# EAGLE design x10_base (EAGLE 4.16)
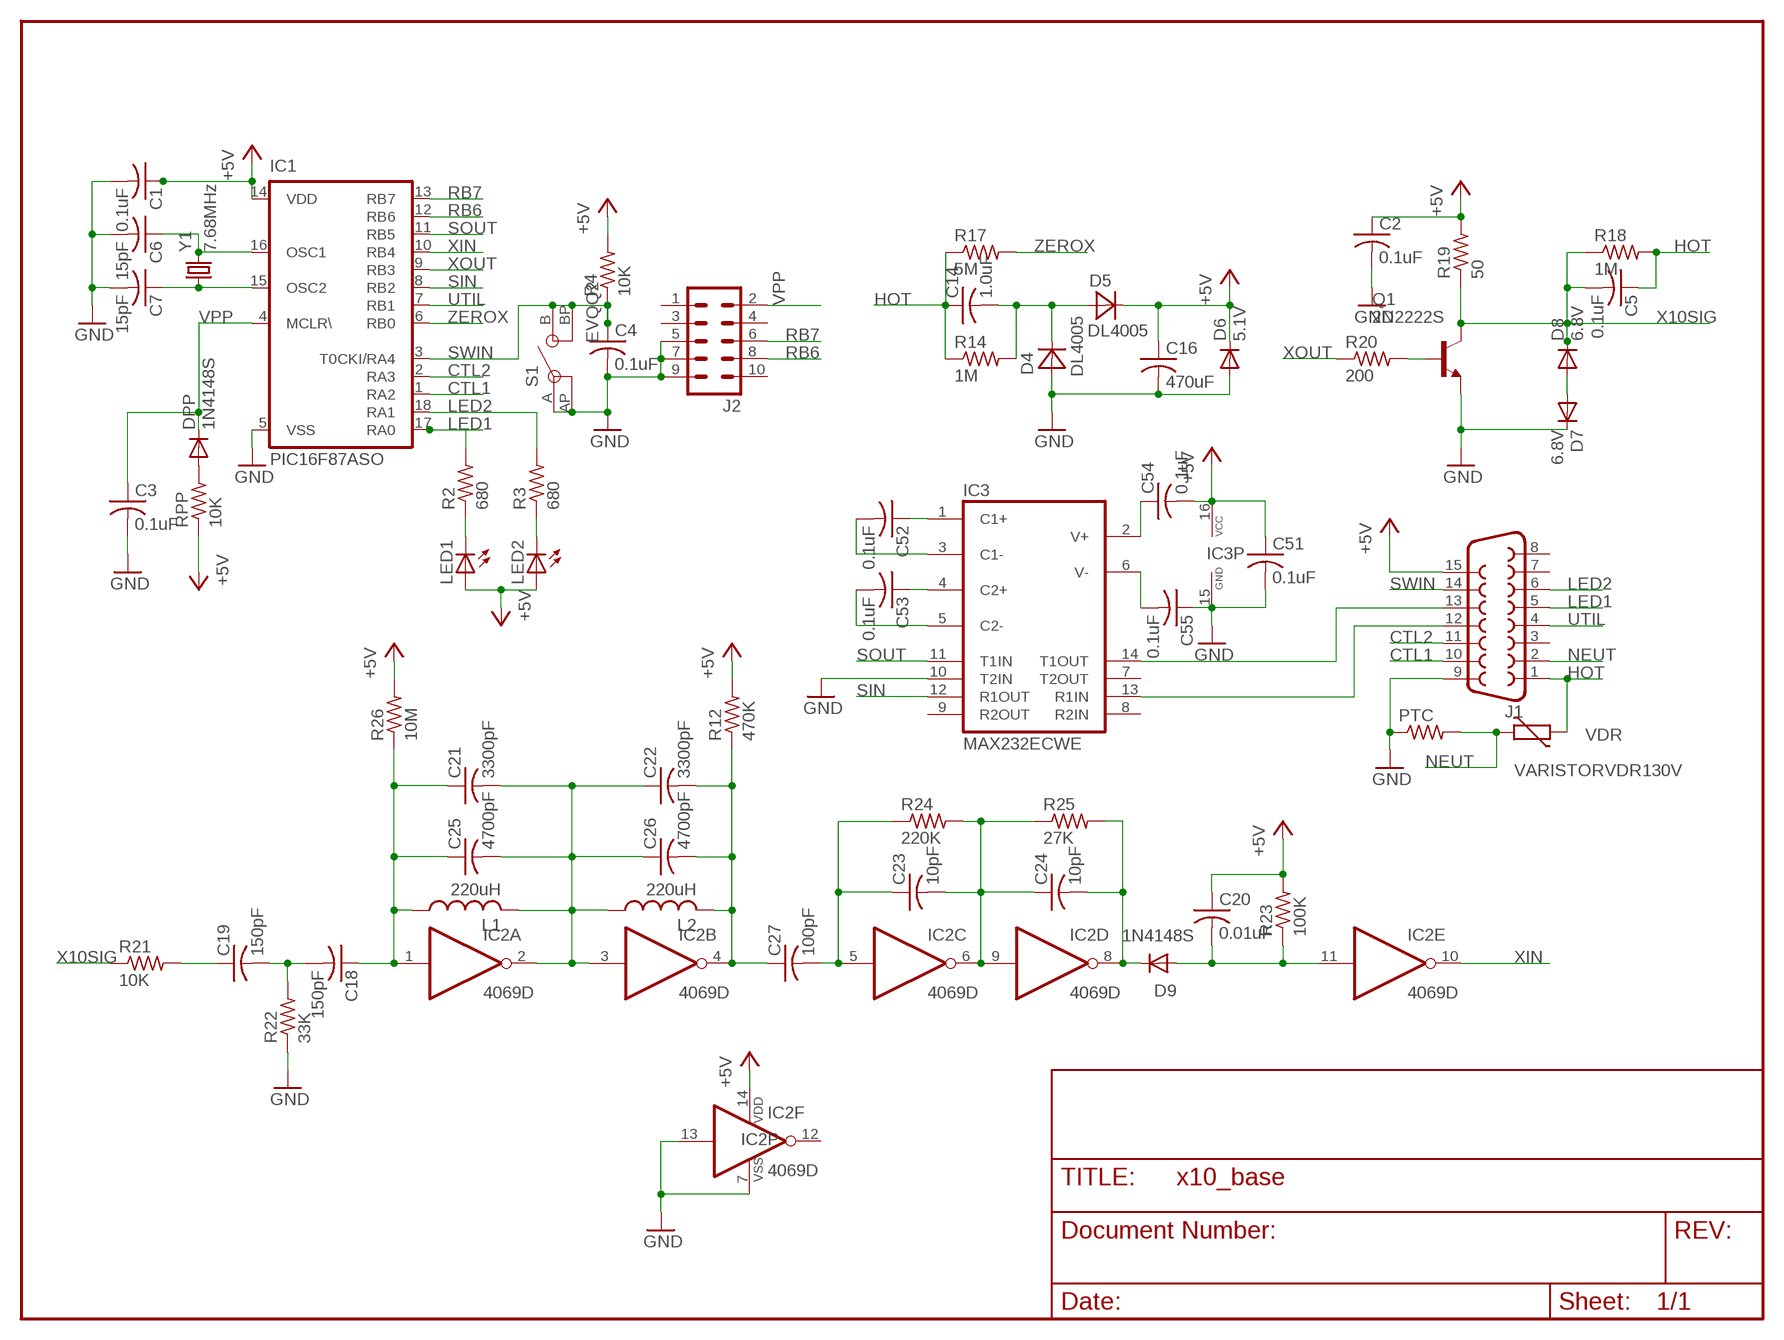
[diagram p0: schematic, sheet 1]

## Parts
C1  0.1uF  C-USC0805  [C0805]
C2  0.1uF  C-USC0805  [C0805]
C3  0.1uF  C-USC0805  [C0805]
C4  0.1uF  C-USC0805  [C0805]
C5  0.1uF  C-US102-043X133  [C102-043X133]
C6  15pF  C-USC0805  [C0805]
C7  15pF  C-USC0805  [C0805]
C14  1.0uF  C-US225-062X268  [C225-062X268]
C16  470uF  C-US275-093X316  [C275-093X316]
C18  150pF  C-USC0805  [C0805]
C19  150pF  C-USC0805  [C0805]
C20  0.01uF  C-USC0805  [C0805]
C21  3300pF  C-USC0805  [C0805]
C22  3300pF  C-USC0805  [C0805]
C23  10pF  C-USC0805  [C0805]
C24  10pF  C-USC0805  [C0805]
C25  4700pF  C-USC0805  [C0805]
C26  4700pF  C-USC0805  [C0805]
C27  100pF  C-USC0805  [C0805]
C51  0.1uF  C-USC0805  [C0805]
C52  0.1uF  C-USC0805  [C0805]
C53  0.1uF  C-USC0805  [C0805]
C54  0.1uF  C-USC0805  [C0805]
C55  0.1uF  C-USC0805  [C0805]
D4  DL4005  [MELF-MLL41]
D5  DL4005  [MELF-MLL41]
D6  5.1V  DIODE-SOD123  [SOD123]
D7  6.8V  DIODE-SOD123  [SOD123]
D8  6.8V  DIODE-SOD123  [SOD123]
D9  1N4148S  [SOD123]
DPP  1N4148S  [SOD123]
IC1  PIC16F87ASO  PIC16F84ASO  [SO-18W]
IC2  4069D  [SO14]
IC3  MAX232ECWE  [SO16L]
J1  F15V  [F15V]
J2  MA05-2  [MA05-2]
L1  220uH  L-US1210  [L1210]
L2  220uH  L-US1210  [L1210]
LED1  LED5MM  [LED5MM]
LED2  LED5MM  [LED5MM]
PTC  R-US_M1206  [M1206]
Q1  2N2222S  [SOT23]
R2  680  R-US_M0805  [M0805]
R3  680  R-US_M0805  [M0805]
R4  10K  R-US_M0805  [M0805]
R12  470K  R-US_M0805  [M0805]
R14  1M  R-US_M0805  [M0805]
R17  5M  R-US_M0805  [M0805]
R18  1M  R-US_M0805  [M0805]
R19  50  R-US_M0805  [M0805]
R20  200  R-US_M0805  [M0805]
R21  10K  R-US_M0805  [M0805]
R22  33K  R-US_M0805  [M0805]
R23  100K  R-US_M0805  [M0805]
R24  220K  R-US_M0805  [M0805]
R25  27K  R-US_M0805  [M0805]
R26  10M  R-US_M0805  [M0805]
RPP  10K  R-US_M0805  [M0805]
S1  EVQQ2  [EVQQ2]
VDR  VARISTORVDR130V  [VDR130V]
Y1  7.68MHz  CRYSTALMM39SL  [MM39SL]

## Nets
+5V: C1.1 C2.1 C16.1 C20.1 C51.1 C54.2 D5.C D6.C IC1.14(VDD) IC2.14(P:VDD) IC3.16(VCC) J1.15 LED1.A LED2.A R4.2 R12.2 R19.2 R23.2 R26.2 RPP.1
CTL1: IC1.1(RA2) J1.10
CTL2: IC1.2(RA3) J1.11
GND: C1.2 C2.2 C3.2 C4.2 C6.2 C7.2 C16.2 C51.2 C55.1 D4.A D6.A D7.C IC1.5(VSS) IC2.7(P:VSS) IC2.13(F:I) IC3.10(T2IN) IC3.15(GND) J1.9 J2.5 J2.7 J2.9 PTC.1 Q1.2(E) R22.1 S1.A S1.AP
HOT: C5.1 C14.1 J1.1 R14.1 R17.1 R18.2 VDR.P$1
LED1: IC1.17(RA0) J1.5 R2.2
LED2: IC1.18(RA1) J1.6 R3.2
N$1: DPP.A RPP.2
N$2: Q1.1(B) R20.2
N$3: C7.1 IC1.15(OSC2) Y1.P$1
N$4: C6.1 IC1.16(OSC1) Y1.P$2
N$5: LED1.K(C) R2.1
N$6: LED2.K(C) R3.1
N$7: IC3.14(T1OUT) J1.13
N$8: C52.1 IC3.1(C1+)
N$9: C14.2 D4.C D5.A R14.2
N$10: C52.2 IC3.3(C1-)
N$12: D7.A D8.A
N$13: C23.1 C27.2 IC2.5(C:I) R24.1
N$14: C23.2 C24.1 IC2.6(C:O) IC2.9(D:I) R24.2 R25.1
N$15: C18.1 C21.1 C25.1 IC2.1(A:I) L1.1 R26.1
N$16: C19.1 R21.2
N$17: C18.2 C19.2 R22.2
N$18: C21.2 C22.1 C25.2 C26.1 IC2.2(A:O) IC2.3(B:I) L1.2 L2.1
N$19: C22.2 C26.2 C27.1 IC2.4(B:O) L2.2 R12.1
N$20: C24.2 D9.C IC2.8(D:O) R25.2
N$21: C20.2 D9.A IC2.11(E:I) R23.1
N$22: C53.1 IC3.4(C2+)
N$23: C53.2 IC3.5(C2-)
N$24: C54.1 IC3.2(V+)
N$25: C55.2 IC3.6(V-)
N$26: IC3.13(R1IN) J1.12
NEUT: J1.2 PTC.2 VDR.P$2
RB6: IC1.12(RB6) J2.8
RB7: IC1.13(RB7) J2.6
SIN: IC1.8(RB2) IC3.12(R1OUT)
SOUT: IC1.11(RB5) IC3.11(T1IN)
SWIN: C4.1 IC1.3(T0CKI/RA4) J1.14 R4.1 S1.B S1.BP
UTIL: IC1.7(RB1) J1.4
VPP: C3.1 DPP.C IC1.4(MCLR\) J2.2
X10SIG: C5.2 D8.C Q1.3(C) R18.1 R19.1 R21.1
XIN: IC1.10(RB4) IC2.10(E:O)
XOUT: IC1.9(RB3) R20.1
ZEROX: IC1.6(RB0) R17.2
Unconnected: IC2.12(F:O) IC3.7(T2OUT) IC3.8(R2IN) IC3.9(R2OUT) J1.3 J1.7 J1.8 J2.1 J2.3 J2.4 J2.10

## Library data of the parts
C1-C7 C14 C16 C18-C27 C51-C55 = rcl:C-US: CAPACITOR, American symbol
D4 D5 = diode:DL4005
D6-D8 = diode:DIODE-: DIODE
D9 DPP = diode:1N4148: DIODE
IC1 = microchip:PIC16F8*: MICROCONTROLLER 8-Bit PIC16F8X Family - CMOS Flash/EEPROM Pin Compatible : PIC16F83, PIC16CR83, PIC16F84A, PIC16CR84 see also PIC16C*
IC2 = 40xx:4069: Hex INVERTER
IC3 = maxim:MAX232ECWE: RS232 TRANSEIVER
J1 = con-subd:F15: SUB-D
J2 = con-lstb:MA05-2: PIN HEADER
L1 L2 = rcl:L-US: INDUCTOR, American symbol
LED1 LED2 = led:LED: LED
PTC R2-R4 R12 R14 R17-R26 RPP = rcl:R-US_: RESISTOR, American symbol
Q1 = transistor-npn:2N2222*: NPN Transistor
S1 = switch:EVQQ2: Panasonic SMT pushbutton
VDR = varistor:VARISTOR: VARISTOR
Y1 = crystal:CRYSTAL: CRYSTAL

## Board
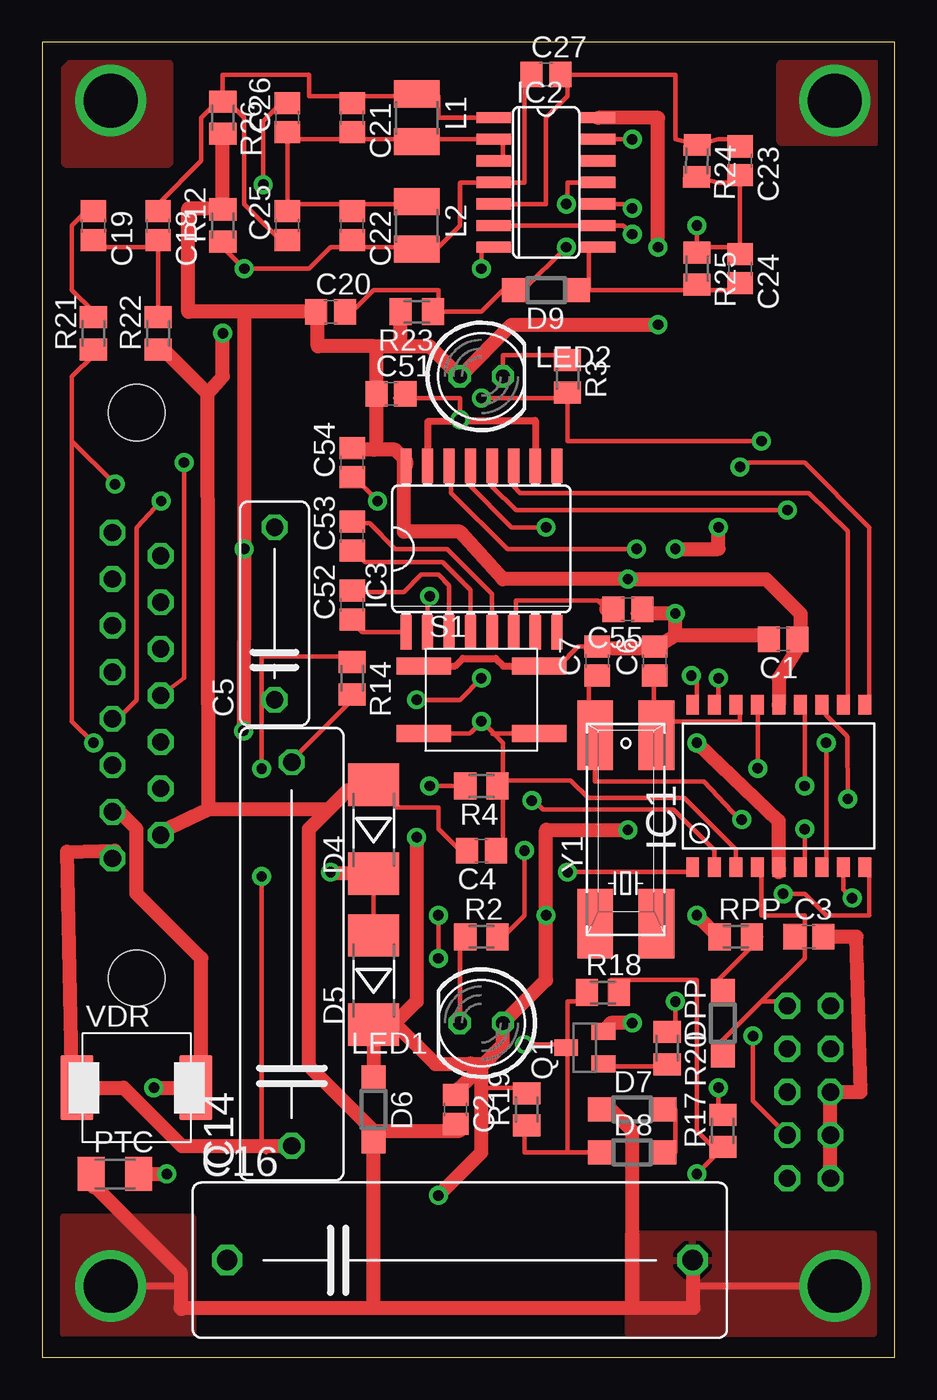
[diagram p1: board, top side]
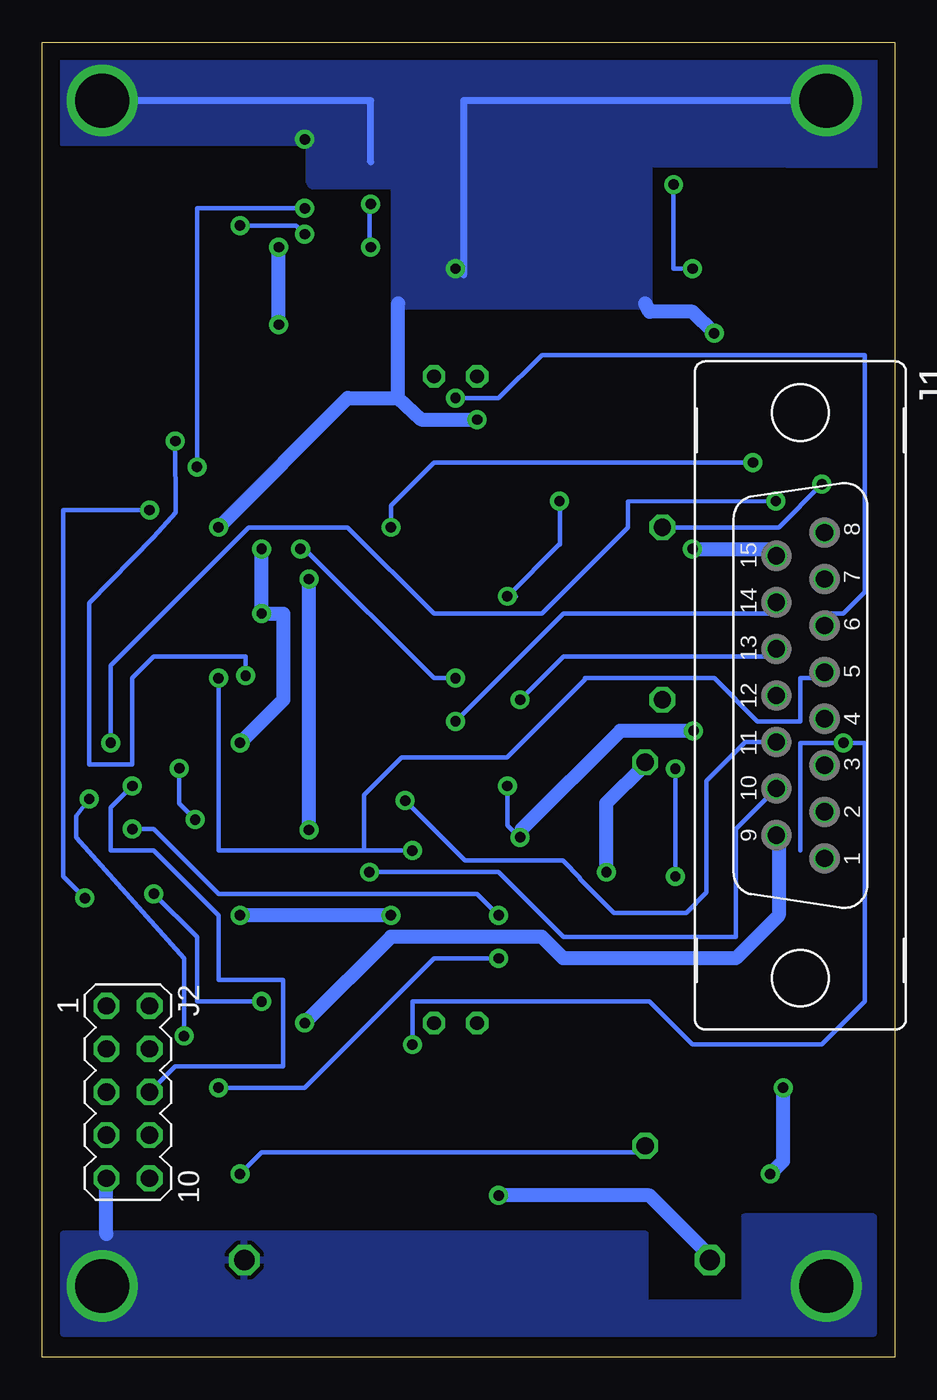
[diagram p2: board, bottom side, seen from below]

Size 50.22 x 77.46 mm. Coordinates in mm from the lower left corner, seen from the top.
Outline: 0,0 50.22,0 50.22,77.46 0,77.46 0,0
Copper layers (1*16): Top 0.035mm / dielectric 1.5mm / Bottom 0.035mm
Design rules "default": minimum track width 10mil, minimum drill 24mil, track to track 10mil, track to pad 10mil, pad to pad 10mil, via to via 10mil, smd to smd 10mil, copper to edge 40mil, drill to drill 8mil, minimum pad ring 10mil, minimum via ring 10mil, stop-mask expansion 4mil, vias tented up to drill 0mil, thermal gap 10mil

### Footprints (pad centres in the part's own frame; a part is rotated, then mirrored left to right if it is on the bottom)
C0805 = smd 1.3 x 1.5: 1 -0.85,0; 2 0.85,0
C102-043X133 = drill 1.016 octagon: 1 -5.08,0; 2 5.08,0
C225-062X268 = drill 1.016 octagon: 1 -11.303,0; 2 11.303,0
C275-093X316 = drill 1.194 octagon: 1 -13.716,0; 2 13.716,0
MELF-MLL41 = smd 2.5 x 3: A 2.625,0; C -2.625,0
SOD123 = smd 1.4 x 1.4: A 1.9,0; C -1.9,0
SO-18W = smd 0.762 x 1.143: 1 -5.08,-4.788; 2 -3.81,-4.788; 3 -2.54,-4.788; 4 -1.27,-4.788; 5 0,-4.788; 6 1.27,-4.788; 7 2.54,-4.788; 8 3.81,-4.788; 9 5.08,-4.788; 10 5.08,4.788; 11 3.81,4.788; 12 2.54,4.788; 13 1.27,4.788; 14 0,4.788; 15 -1.27,4.788; 16 -2.54,4.788; 17 -3.81,4.788; 18 -5.08,4.788
SO14 = smd 0.66 x 2.032: 1 -3.81,-3.073; 2 -2.54,-3.073; 3 -1.27,-3.073; 4 0,-3.073; 5 1.27,-3.073; 6 2.54,-3.073; 7 3.81,-3.073; 8 3.81,3.073; 9 2.54,3.073; 10 1.27,3.073; 11 0,3.073; 12 -1.27,3.073; 13 -2.54,3.073; 14 -3.81,3.073
SO16L = smd 0.66 x 2.032: 1 -4.445,-4.902; 2 -3.175,-4.902; 3 -1.905,-4.902; 4 -0.635,-4.902; 5 0.635,-4.902; 6 1.905,-4.902; 7 3.175,-4.902; 8 4.445,-4.902; 9 4.445,4.902; 10 3.175,4.902; 11 1.905,4.902; 12 0.635,4.902; 13 -0.635,4.902; 14 -1.905,4.902; 15 -3.175,4.902; 16 -4.445,4.902
F15V = drill 1.016 octagon: 1 9.601,1.422; 2 6.858,1.422; 3 4.115,1.422; 4 1.372,1.422; 5 -1.372,1.422; 6 -4.115,1.422; 7 -6.858,1.422; 8 -9.601,1.422; 9 8.23,-1.422; 10 5.486,-1.422; 11 2.743,-1.422; 12 0,-1.422; 13 -2.743,-1.422; 14 -5.486,-1.422; 15 -8.23,-1.422 | hole 3.302: 16.662,0; -16.662,0
MA05-2 = drill 1.016 octagon: 1 -5.08,-1.27; 2 -5.08,1.27; 3 -2.54,-1.27; 4 -2.54,1.27; 5 0,-1.27; 6 0,1.27; 7 2.54,-1.27; 8 2.54,1.27; 9 5.08,-1.27; 10 5.08,1.27
L1210 = smd 1.6 x 2.7: 1 -1.4,0; 2 1.4,0
LED5MM = drill 0.813 octagon: A -1.27,0; K 1.27,0
M1206 = smd 1.6 x 2: 1 -1.4,0; 2 1.4,0
SOT23 = smd 1 x 1.4: 1 -0.95,-1.1; 2 0.95,-1.1; 3 0,1.1
M0805 = smd 1.3 x 1.6: 1 -0.95,0; 2 0.95,0
EVQQ2 = smd 3.2 x 1: A -3.4,2; AP 3.4,2; B -3.4,-2; BP 3.4,-2
VDR130V = smd 1.93 x 3.81: P$1 -3.5,0; P$2 3.5,0
MM39SL = smd 4.1 x 2.1: P$1 5.55,1.8; P$2 5.55,-1.8; P$3 -5.55,-1.8; P$4 -5.55,1.8

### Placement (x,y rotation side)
C1  43.65,42.29 180 top
C2  24.35,14.6 270 top
C3  45.17,24.76 0 top
C4  25.87,29.84 180 top
C5  13.68,43.81 90 top
C6  36.08,41.02 90 top
C7  32.7,41.02 90 top
C14  14.69,23.74 90 top
C16  24.6,5.71 0 top
C18  6.82,66.67 270 top
C19  3.01,66.67 270 top
C20  16.98,61.59 0 top
C21  18.25,73.02 270 top
C22  18.25,66.67 270 top
C23  41.11,70.48 270 top
C24  41.11,64.13 270 top
C25  14.44,66.67 90 top
C26  14.44,73.02 90 top
C27  29.68,75.56 0 top
C51  20.54,56.76 0 top
C52  18.25,44.32 90 top
C53  18.25,48.38 90 top
C54  18.25,52.7 90 top
C55  34.51,44.06 180 top
D4  19.52,31.11 90 top
D5  19.52,22.22 90 top
D6  19.52,14.6 270 top
D7  34.76,14.6 0 top
D8  34.76,12.06 0 top
D9  29.68,62.86 180 top
DPP  40.09,19.68 90 top
IC1  43.4,33.65 0 top
IC2  29.68,69.21 270 top
IC3  25.87,47.62 0 top
J1  5.55,38.98 270 bottom
J2  45.17,15.62 270 bottom
L1  22.06,73.02 270 top
L2  22.06,66.67 270 top
LED1  25.87,19.68 180 top
LED2  25.87,57.78 0 top
PTC  4.28,10.79 0 top
Q1  31.97,18.23 90 top
R2  25.87,24.76 0 top
R3  30.95,57.78 270 top
R4  25.87,33.65 180 top
R12  10.63,66.67 90 top
R14  18.25,40 270 top
R17  40.09,13.33 90 top
R18  33.03,21.48 0 top
R19  28.54,14.6 90 top
R20  36.82,18.21 270 top
R21  3.01,60.32 90 top
R22  6.82,60.32 90 top
R23  22.06,61.59 180 top
R24  38.57,70.48 268.8 top
R25  38.57,64.13 270 top
R26  10.63,73.02 270 top
RPP  40.86,24.76 0 top
S1  25.87,38.73 0 top
VDR  5.55,15.87 0 top
Y1  34.38,31.08 90 top

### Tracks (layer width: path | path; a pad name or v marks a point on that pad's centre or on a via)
+5V  (via drill 0.61)
  Top 0.254: 10.63,67.43 R12.2 10.63,67.69 | C20.1 15.71,61.59 | 44.67,42.54 C1.1 | 21.3,52.7 21.17,53.08 | 24.6,15.87 C2.1 | 20.79,19.68 D5.C | v22.82,33.65 R4.2 | 25.87,15.87 28.41,15.87 R19.2 | 39.84,24.76 RPP.1
  Top 0.813: IC1.14 43.4,40 44.67,42.03 C1.1 | 19.52,16.38 D6.C D5.C 20.82,19.59 23.15,17.27 25.29,17.27 | IC3.16 21.42,52.83 21.17,53.08 20.79,53.46 19.52,53.46 | C54.2 18.25,53.46 19.52,53.46 | 19.52,53.46 19.69,53.63 C51.1 19.69,59.39 19.52,59.56 | 19.52,59.56 16.22,59.56 16.22,61.59 C20.1 | R23.2 21.11,59.62 21.04,59.56 | 19.52,59.56 21.04,59.56 | 15.71,61.59 11.9,61.59 | 11.9,61.59 8.6,61.59 8.6,67.69 10.63,67.69 | R12.2 R26.2 | v36.28,65.4 36.28,73.02 IC2.14 | 44.67,42.54 44.67,43.81 42.63,45.84 v34.51,45.84 27.14,45.84 24.6,48.64 21.3,48.64 21.3,52.7 | 25.87,17.14 27.14,18.41 LED1.A 29.68,22.22 v29.68,26.03 29.68,31.06 v34.51,31.06 | 25.87,17.14 24.6,15.87 | v23.33,9.52 25.87,12.06 25.87,15.87 25.87,17.14 | 11.9,61.59 v11.9,47.62 v11.85,36.9 | 20.79,19.68 22.06,20.95 v22.06,30.63 | 21.04,59.56 22.82,59.56 LED2.A 27.65,60.83 v36.28,60.83 | 25.29,17.27 25.97,17.27 | 25.29,17.27 25.26,17.29 25.21,17.29 | v38.57,26.03 39.84,24.76
  Bottom 0.254: C16.1 10.63,5.71 | v22.06,30.63 22.06,30.55 22.82,31.31 v22.82,33.65
  Bottom 0.813: 10.63,5.71 14.44,9.52 v23.33,9.52 | v11.9,47.62 6.82,47.62 J1.15 | v34.51,31.06 v34.51,45.84 | v36.28,60.83 v36.28,65.4 | v11.85,36.9 16.17,36.9 21.96,31.11 v22.06,30.63 | v29.68,26.03 v38.57,26.03
CTL1  (via drill 0.61)
  Top 0.254: v30.95,28.57 38.57,28.57 IC1.1
  Bottom 0.254: v30.95,28.57 23.33,28.57 19.52,24.76 9.36,24.76 9.36,31.11 J1.10 6.82,33.65
CTL2  (via drill 0.61)
  Top 0.254: 39.59,28.57 IC1.2 39.55,28.86 39.48,28.93 39.59,29.03 39.59,29.89 37.2,32.28 29.5,32.28 28.99,32.79 v28.84,32.79
  Bottom 0.254: J1.11 8.8,36.24 11.09,33.96 11.09,27.38 12.28,26.18 16.55,26.18 18.53,28.16 18.53,28.24 19.54,29.26 25.31,29.26 v28.84,32.79
GND  (via drill 0.61, 3.17)
  Top 0.254: 38.37,5.68 C16.2 | 24.6,13.33 C2.2 | 33.49,14.6 D7.C | 7.2,59.3 R22.1 | 6.95,30.91 J1.9 | 18,33.4 D4.A 20.79,33.65 20.79,32.38 23.33,32.38 23.33,31.11 24.6,29.84 C4.2 | D6.A 19.52,13.33 | 32.3,41.78 C7.2 32.7,41.85 | 43.37,28.57 IC1.5 | 42.38,42.54 C1.2 | 36.11,41.78 C6.2 | v24.6,55.24 24.6,56.51 20.79,56.51 C51.2 | v25.87,64.13 25.87,65.4 IC2.7 | IC2.13 v34.76,71.75 | C55.1 34.76,43.81 | S1.AP 30.43,40.73 31.56,41.85 32.7,41.85 | 32.7,41.85 32.73,41.83
  Top 0.406: 8.01,5 8.01,5.08 | 8.01,5 8.14,5 | v4.03,4.19 8.01,4.19 8.01,5 | v46.7,4.19 38.29,4.19 38.29,5.71 | 43.37,28.57 43.45,28.57 | IC3.10 29.04,55.19 24.62,55.19 24.62,55.24 v24.6,55.24 24.6,55.11 22.7,55.11 IC3.15 | S1.A 24.34,40.73 24.78,41.17 26.71,41.17 27.16,40.71 29.25,40.71 S1.AP
  Top 0.813: J2.9 J2.7 J2.5 48.22,15.62 47.97,24.76 C3.2 | 8.19,2.92 8.14,2.92 | 8.19,2.92 19.52,2.92 | 19.52,2.92 34.76,2.92 | 34.76,2.92 38.37,2.89 38.37,5.68 | PTC.1 3.01,10.79 3.01,10.03 3.11,10.03 8.14,5 8.14,2.89 8.19,2.84 8.19,2.92 | IC1.5 43.4,28.57 | 19.52,2.92 D6.A | 24.6,13.33 19.52,13.33 15.71,17.14 15.71,31.11 16.84,32.24 | 33.49,14.6 34.76,13.33 34.76,2.92 | v34.76,19.68 33.49,19.68 Q1.2 | 9.74,56.76 7.2,59.3 | 9.79,32.28 9.74,56.76 | 9.79,32.28 6.95,30.91 | 16.84,32.24 18,33.4 | 32.3,41.78 36.11,41.78 37.3,42.54 | 43.37,28.57 43.37,31.59 v38.57,36.19 | 37.3,42.54 42.38,42.54 | 37.3,42.54 v37.3,43.81 35.37,43.81 C55.1 | v37.3,47.62 39.84,47.62 v39.84,48.89 | 9.74,56.76 10.63,57.78 v10.63,60.32 | 16.84,32.24 16.83,32.24 16.83,32.28 9.79,32.28
  Bottom 0.254: J1.9 6.82,31.11 | 25.39,64.13 v25.87,64.13
  Bottom 0.406: v46.7,74.04 30.87,74.04 30.87,70.4 | v4.03,74.04 25.39,74.04 25.39,64.13 25.39,63.77
  Bottom 0.813: 46.44,7.23 J2.9 | v34.76,19.68 29.68,24.76 20.79,24.76 19.52,23.49 9.36,23.49 6.82,26.03 6.82,31.11 | v38.57,36.19 36.03,38.73 36.03,43.81 v37.3,43.81 v37.3,47.62 | v24.6,55.24 27.9,55.24 29.25,56.51 | 29.25,56.51 29.25,62.1 | v39.84,48.89 32.22,56.51 29.25,56.51 | v10.63,60.32 11.9,61.59 14.44,61.59 14.69,62.1
  pour Top: 43.65,71.75 43.65,76.07 48.98,76.07 48.98,71.75
  pour Top: 1.49,70.48 7.33,70.48 7.33,76.07 1.74,76.07 1.49,75.81
  pour Top: 1.23,1.39 1.23,8.25 8.85,8.25 8.85,1.39
  pour Top: 48.98,1.39 48.98,7.23 34.51,7.23 34.51,1.39
  pour Bottom: 1.23,1.39 1.23,8.25 8.85,8.25 8.85,3.17 14.69,3.17 14.69,7.23 48.98,7.23 48.98,1.39
  pour Bottom: 0.98,76.32 0.98,70.48 6.31,70.48 0.98,70.48 14.69,70.48 14.69,62.1 29.27,62.1 29.27,69.21 34.25,69.21 34.25,71.75 48.98,71.75 48.98,76.32
HOT  (via drill 0.61)
  Top 0.254: VDR.P$1 1.74,17.14 | 4.28,29.84 J1.1 | 12.92,38.73 12.92,41.27 18.25,41.27 R14.1 | v12.92,28.32 12.92,12.44 13.17,12.06 | v12.92,34.67 12.92,38.73 | 12.92,38.73 C5.1 | 39.84,12.06 38.57,13.33 38.57,22.22 33.49,22.22 R18.2 | v38.57,10.79 39.84,12.06 | 39.84,12.06 R17.1
  Top 0.813: 1.74,17.14 1.46,29.76 4.28,29.84 | C14.1 12.92,12.44 8.22,12.44 4.79,15.87 VDR.P$1
  Bottom 0.254: v12.92,28.32 v12.92,34.67 | v38.57,10.79 37.3,12.06 14.44,12.06 C14.1
LED1  (via drill 0.61)
  Top 0.254: v39.84,40 39.84,38.73 IC1.17 | v28.41,29.84 28.41,26.03 27.14,24.76 R2.2
  Bottom 0.254: v39.84,40 39.84,29.84 31.31,29.84 | 31.31,29.84 v28.41,29.84 | J1.5 4.28,40 5.55,40 5.55,37.46 8.09,37.46 10.63,40 18.25,40 18.25,39.92 22.85,35.33 29.04,35.33 31.25,33.12 31.25,29.94 31.31,29.89 31.31,29.84
LED2  (via drill 0.61)
  Top 0.254: v42.38,53.97 30.95,53.97 30.95,56.51 | v25.87,56.51 30.95,56.51 | 30.95,56.51 R3.2 | v38.24,40.15 38.57,40 38.57,38.73 IC1.18
  Bottom 0.254: v42.38,53.97 42.35,49.75 43.65,48.31 47.46,44.42 47.46,34.92 44.92,34.92 44.92,40 43.65,41.27 38.24,41.27 v38.24,40.15 38.24,40 | v25.87,56.51 23.33,56.51 20.79,59.05 1.74,59.05 1.74,45.08 3.01,43.81 4.28,43.81 J1.6
N$1
  Top 0.254: DPP.A 39.84,22.22 42.38,24.76 RPP.2
N$2
  Top 0.254: Q1.1 33.49,17.14 36.03,17.14 R20.2
N$3  (via drill 0.61)
  Top 0.254: C7.1 32.22,40 32.22,37.46 Y1.P$1 32.58,36.72 32.55,36.7 32.55,33.9 38.98,33.9 41.06,31.67 | v42.15,34.69 42.15,38.44
  Top 0.406: 42.15,38.44 IC1.15 | 41.06,31.67 v41.21,31.67 | 32.58,36.7 Y1.P$1
  Bottom 0.254: v42.15,34.69 42.15,32.61 v41.21,31.67
N$4
  Top 0.254: 36.03,37.46 41.11,37.46 41.11,38.73 IC1.16 | 36.03,37.46 36.03,40 | Y1.P$2 36.03,37.46
  Top 0.813: 36.03,40 C6.1
N$5
  Top 0.254: LED1.K 24.6,24.76 R2.1
N$6
  Top 0.254: LED2.K 27.14,59.05 30.95,59.05 R3.1
N$7  (via drill 0.61)
  Top 0.254: v35.01,47.62 27.39,47.62 24.09,50.92 24.09,52.45 24.02,52.52 IC3.14 | v25.87,40 24.6,38.73 v22.06,38.73
  Bottom 0.254: v25.87,40 27.14,40 34.76,47.62 v35.01,47.62 | v22.06,38.73 19.52,41.27 6.82,41.27 J1.13
N$8
  Top 0.254: C52.1 18.25,43.3 18.83,42.72 IC3.1
N$9  (via drill 0.61)
  Top 0.254: D5.A D4.C | R14.2 18.25,38.73 14.44,34.92 C14.2
  Top 0.813: D4.C 17.06,28.48 v16.98,28.57
  Bottom 0.813: C14.2 14.69,34.92 16.98,32.63 v16.98,28.57
N$10
  Top 0.254: IC3.3 23.96,45.46 23.33,46.1 22.31,46.1 21.3,45.08 18.5,45.08 18.42,45.17 C52.2
N$12
  Top 0.254: D8.A 37.3,12.06 37.3,14.6 D7.A
N$13
  Top 0.254: 30.95,75.56 37.3,75.56 37.3,71.75 R24.1 39.84,71.75 41.11,71.75 C23.1 | 30.95,75.56 30.95,74.29 29.68,73.02 29.68,67.94 IC2.5 | 30.95,75.56 C27.2
N$14  (via drill 0.61)
  Top 0.254: 38.57,65.4 41.11,65.4 | 41.11,69.21 39.84,69.21 R24.2 | 41.11,65.4 41.11,69.21 | 41.11,65.4 C24.1 | 41.11,69.21 C23.2 | IC2.6 IC2.9 34.25,66.67 v34.76,66.16 | v38.57,66.67 38.57,65.4 | 38.57,65.4 R25.1
  Bottom 0.254: v34.76,66.16 35.27,66.67 v38.57,66.67
N$15
  Top 0.254: 18.25,74.29 20.79,74.29 L1.1 23.33,74.29 23.33,73.02 IC2.1 | 10.63,74.29 9.36,73.02 9.36,70.48 6.82,67.94 C18.1 | 10.63,74.29 11.9,73.02 11.9,67.94 14.44,65.4 C25.1 | 18.25,74.29 15.71,74.29 15.71,75.56 10.63,75.56 10.63,74.29 | 18.25,74.29 C21.1 | 10.63,74.29 R26.1
N$16
  Top 0.254: C19.1 3.01,67.94 1.74,66.67 1.74,62.86 3.01,61.59 R21.2
N$17
  Top 0.254: 6.82,65.4 3.01,65.4 C19.2 | R22.2 6.82,65.4 | 6.82,65.4 C18.2
N$18
  Top 0.254: IC2.3 27.14,70.48 27.14,71.75 IC2.2 23.33,71.75 L1.2 20.79,71.75 18.25,71.75 | 14.44,67.94 14.44,71.75 | 18.25,67.94 20.79,67.94 L2.1 | 14.44,67.94 18.25,67.94 | C25.2 14.44,67.94 | 18.25,67.94 C22.1 | 14.44,71.75 18.25,71.75 | 18.25,71.75 C21.2 | 14.44,71.75 C26.1
N$19  (via drill 0.61)
  Top 0.254: v13.02,69.08 13.02,72.82 14.44,74.29 C26.2 | R12.1 10.63,65.4 v11.9,64.13 15.71,64.13 16.98,65.4 18.25,65.4 | 18.25,65.4 20.79,65.4 L2.2 23.33,65.4 24.6,66.67 24.6,69.21 IC2.4 28.41,69.21 28.41,75.56 C27.1 | 18.25,65.4 C22.2
  Bottom 0.254: v13.02,69.08 13.04,64.13 v11.9,64.13
N$20
  Top 0.254: 38.57,62.86 41.11,62.86 C24.2 | 32.22,62.86 32.22,65.4 IC2.8 | 32.22,62.86 38.57,62.86 | 38.57,62.86 R25.2 | D9.C 32.22,62.86
N$21  (via drill 0.61)
  Top 0.254: C20.2 18.25,61.59 19.52,62.86 23.33,62.86 23.33,61.59 23.08,61.59 | 23.08,61.59 R23.1 | 23.08,61.59 25.87,61.59 27.14,62.86 D9.A 28.33,62.86 v30.87,65.4 30.9,65.42 | 30.95,67.94 30.9,67.94 | 30.95,67.94 30.95,69.21 IC2.11 | v30.87,67.94 30.95,67.94
  Bottom 0.254: 30.9,67.96 30.9,67.94 v30.87,67.94 30.95,67.94 30.95,65.4 v30.87,65.4 30.9,65.4
N$22
  Top 0.254: 18.5,47.62 18.42,47.53 C53.1 18.25,47.62 19.01,46.86 23.58,46.86 25.23,45.21 IC3.4
N$23
  Top 0.254: IC3.5 26.5,44.95 23.84,47.62 20.79,47.62 19.27,49.14 18.25,49.14 C53.2
N$24  (via drill 0.61)
  Top 0.254: IC3.2 22.7,44.7 v22.82,44.83 | 18.25,51.68 C54.1 18.25,51.91 18.27,51.94 19.75,50.47 v19.75,50.44
  Bottom 0.254: 22.31,44.83 v22.82,44.83 19.77,47.87 19.72,47.87 19.72,50.44 v19.75,50.44
N$25
  Top 0.254: IC3.6 27.72,42.72 27.65,42.79 27.9,43.05 27.9,44.57 32.73,44.57 33.24,44.06 | C55.2 33.49,44.06 32.98,44.57
  Top 0.813: 33.24,44.06 C55.2
N$26  (via drill 0.61)
  Top 0.254: v29.68,48.89 27.65,48.89 25.11,51.43 25.11,52.45 25.18,52.52 IC3.13 | v8.34,52.7 8.34,40 J1.12 6.82,38.73
  Bottom 0.254: v8.34,52.7 27.14,52.7 29.68,50.16 v29.68,48.89
NEUT  (via drill 0.61)
  Top 0.254: PTC.2 5.55,10.79 | 4.28,32.38 J1.2 | VDR.P$2 9.36,17.14
  Top 0.813: 4.28,32.38 5.55,31.11 5.55,27.3 9.36,23.49 9.36,17.14 | 5.55,10.79 v7.33,10.79 | v6.57,15.87 VDR.P$2
  Bottom 0.813: v6.57,15.87 6.57,11.55 v7.33,10.79
RB6  (via drill 0.61)
  Top 0.254: 45.94,38.73 IC1.12 46.19,38.73 46.16,37.84 47.44,36.57 v47.46,32.89 | v41.87,18.92 41.87,15.11 J2.8
  Bottom 0.254: v47.46,32.89 48.22,31.87 48.22,30.6 41.87,23.49 v41.87,18.92
RB7  (via drill 0.61)
  Top 0.254: 44.67,38.73 IC1.13 44.92,38.73 v44.92,33.65
  Bottom 0.254: v44.92,33.65 46.19,32.38 46.19,29.84 43.65,29.84 39.84,26.03 39.84,22.22 36.03,22.22 36.03,17.14 42.38,17.14 J2.6
SIN  (via drill 0.61)
  Top 0.254: IC1.8 47.21,27.55 v47.71,27.05 | IC3.12 26.5,51.3 27.9,49.91 v43.9,49.91
  Bottom 0.254: v47.71,27.05 48.98,28.32 48.98,49.91 v43.9,49.91
SOUT
  Top 0.254: IC3.11 27.77,51.3 28.16,50.92 45.17,50.92 47.46,48.66 47.46,38.73 IC1.11
SWIN  (via drill 0.61)
  Top 0.254: 40.86,28.57 IC1.3 40.86,29.92 37.83,32.94 32.17,32.94 31.13,33.98 27.11,33.98 27.04,34.06 27.14,34.06 | 27.14,34.06 27.14,36.19 26.57,36.76 | 27.14,34.06 27.14,33.65 | 27.14,33.65 27.14,29.84 C4.1 | 27.14,33.65 R4.1 | 26.57,36.76 v25.87,37.46 25.87,37.41 25.26,36.8 25.23,36.8 25.16,36.73 S1.B | 26.57,36.76 26.54,36.73 | 26.54,36.73 S1.BP | 26.54,36.73 26.53,36.72
  Bottom 0.254: v25.87,37.46 19.52,43.81 6.82,43.81 J1.14
UTIL  (via drill 0.61)
  Top 0.254: 45.94,28.57 IC1.7 46.19,28.57 v46.19,36.19 | v7,50.44 5.55,48.89 5.55,38.73 4.28,37.46 J1.4
  Bottom 0.254: v7,50.44 15.71,50.41 15.71,48.89 20.79,43.81 27.14,43.81 32.22,48.89 38.06,48.89 46.19,40.76 v46.19,36.19
VPP
  Top 0.254: 44.92,24.76 44.92,26.03 42.38,26.03 42.38,28.57 IC1.4 | 42.38,20.95 44.92,23.49 44.92,24.76 | 42.38,20.95 39.84,18.41 DPP.C | 44.92,24.76 C3.1 | 42.38,20.95 43.65,20.95 J2.2
X10SIG  (via drill 0.61)
  Top 0.254: C5.2 13.17,48.89 | 30.95,12.06 28.41,12.06 28.41,13.33 R19.1 | 30.95,12.06 D8.C | 30.95,18.41 30.95,12.06 | 30.95,18.41 30.95,20.95 32.22,20.95 R18.1 | 1.74,53.97 1.74,57.78 3.01,59.05 R21.1 | 1.74,53.97 v4.28,51.43 | v28.41,18.41 30.95,18.41 | v3.01,36.19 1.74,37.46 1.74,53.97 | 30.95,18.41 Q1.3
  Bottom 0.254: v4.28,51.43 6.82,48.89 C5.2 | v28.41,18.41 28.41,20.95 14.44,20.95 11.9,18.41 4.28,18.41 1.74,20.95 1.74,36.19 v3.01,36.19 5.55,36.19 5.55,29.84
XIN  (via drill 0.61)
  Top 0.254: v41.11,52.45 41.11,52.7 43.65,52.7 | 43.65,52.7 43.9,52.7 | 48.48,38.73 48.73,38.48 48.69,38.44 IC1.10 48.73,38.73 48.73,48.89 44.92,52.7 43.65,52.7 | IC2.10 34.76,67.94 v34.76,67.69
  Bottom 0.254: v41.11,52.45 41.11,67.69 v34.76,67.69
XOUT  (via drill 0.61)
  Top 0.254: 48.48,28.57 IC1.9 48.73,28.57 48.73,26.03 46.19,26.03 44.92,27.3 v43.65,27.3 | v37.3,20.95 37.3,19.68 R20.1
  Bottom 0.254: v43.65,27.3 41.11,24.76 41.11,20.95 v37.3,20.95
ZEROX  (via drill 0.61)
  Top 0.254: v44.92,31.11 44.92,28.57 IC1.6 | v39.84,15.87 39.84,14.6 R17.2 | v23.33,23.49 v23.33,26.03
  Bottom 0.254: v39.84,15.87 34.76,15.87 27.14,23.49 v23.33,23.49 | v23.33,26.03 24.6,27.3 39.84,27.3 43.65,31.11 v44.92,31.11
